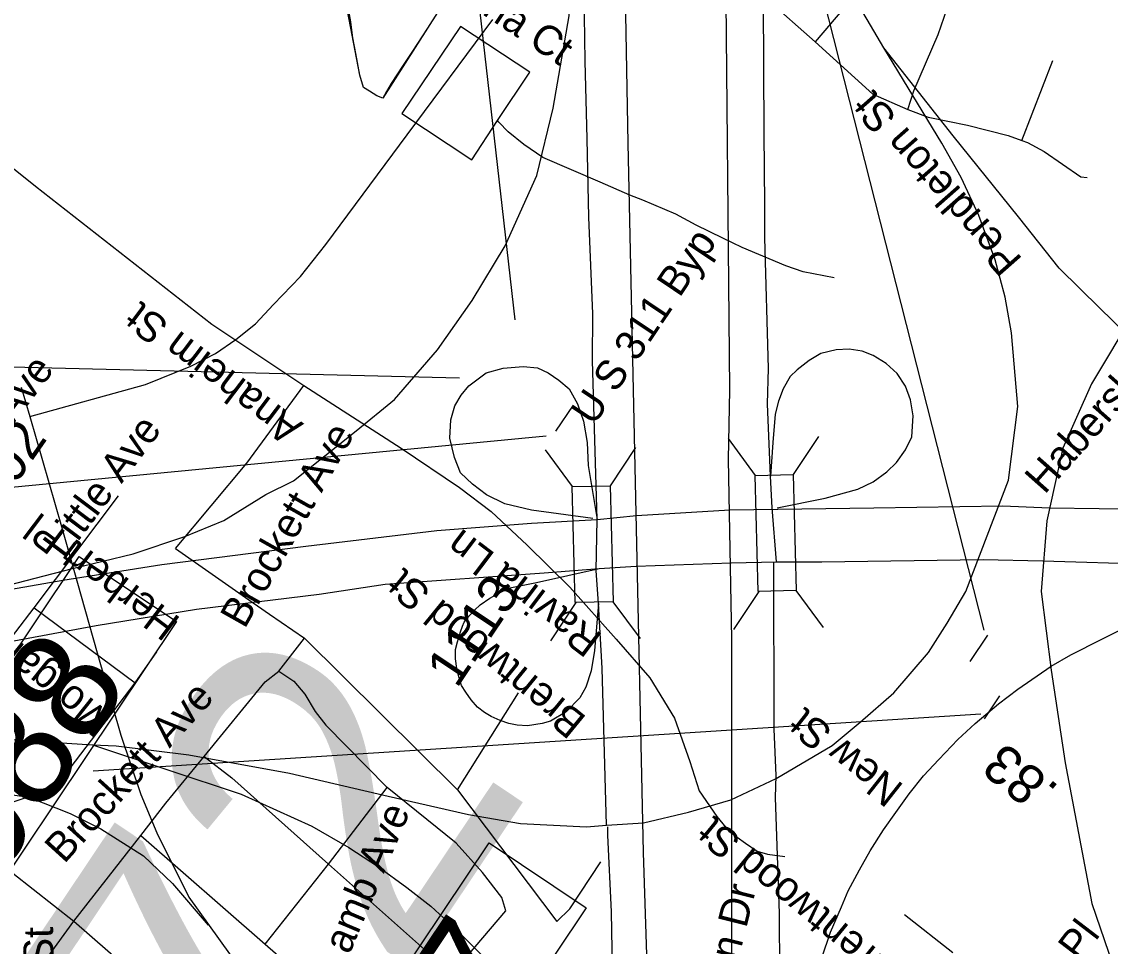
# Model space of a CAD drawing. Extents: x 1716282 to 1717158, y 799307 to 801078.
# Drawn here: x 1716807.8 to 1716858.4, y 800816.9 to 800859.9 of the extents above; entities that cross this region are included whole.
import ezdxf

# ---------------------------------------------------------------- set-up
doc = ezdxf.new("R2010")
doc.units = 0
for name, color, linetype in [('Exist Hydrographic Misc Water Feature', 7, 'Continuous'), ('Exist Road Non-System Structure Non-Sys Other Number Label', 7, 'Continuous'), ('Exist Road Non-System Type 51', 7, 'Continuous'), ('Exist Road Non-System Type 51 Label', 7, 'Continuous'), ('Exist Road Primary Interstate Divided Center Attributed', 7, 'Continuous'), ('Exist Road Primary US Mileage Hundredths English Label', 7, 'Continuous'), ('Exist Road Primary US Structure Ovrhead Sign CELL', 7, 'Continuous'), ('Exist Road Primary US Structure Standard Bridge CELL', 7, 'Continuous'), ('Exist Road Primary US Structure Standard Bridge Number Label', 7, 'Continuous'), ('Exist Road Secondary Mileage Hundredths English Label', 7, 'Continuous'), ('Exist Road Secondary Type 51 Attributed', 7, 'Continuous'), ('Exist Road Secondary Type 51 Label', 7, 'Continuous'), ('Exist Road Secondary Type 51 Number Label', 7, 'Continuous'), ('Prop Road Primary US Projected', 7, 'Continuous'), ('Prop Road Secondary Projected', 7, 'Continuous')]:
    doc.layers.add(name, color=color, linetype=linetype)

msp = doc.modelspace()

# ---------------------------------------------------------------- linework, layer by layer
at = {"layer": 'Exist Hydrographic Misc Water Feature'}
for points in [[(1716823.233, 800862.91), (1716824.255, 800862.247), (1716825.709, 800861.29), (1716826.428, 800860.798), (1716827.147, 800860.308), (1716826.681, 800859.574), (1716824.599, 800856.321), (1716824.327, 800856.437), (1716823.975, 800856.643), (1716823.711, 800856.822), (1716823.54, 800857.395), (1716822.742, 800861.525), (1716822.712, 800861.686), (1716822.675, 800861.888), (1716822.839, 800862.231), (1716823.233, 800862.91)], [(1716827.147, 800860.308), (1716826.681, 800859.574), (1716825.984, 800858.502), (1716825.509, 800857.807), (1716824.994, 800857.001), (1716824.771, 800856.626), (1716824.599, 800856.321), (1716824.327, 800856.437), (1716823.975, 800856.643), (1716823.711, 800856.822), (1716823.54, 800857.395), (1716823.352, 800858.403), (1716823.215, 800859.129), (1716823.118, 800859.861), (1716823.019, 800860.386)], [(1716829.931, 800855.28), (1716831.427, 800857.524), (1716828.208, 800859.652), (1716825.484, 800855.611), (1716828.726, 800853.466), (1716829.931, 800855.28)], [(1716829.931, 800855.28), (1716831.427, 800857.524), (1716828.208, 800859.652), (1716825.484, 800855.611), (1716828.726, 800853.466), (1716829.931, 800855.28)], [(1716845.561, 800847.974), (1716844.107, 800848.264), (1716843.306, 800848.53), (1716841.289, 800849.383), (1716840.391, 800849.818), (1716839.152, 800850.421), (1716838.199, 800850.93), (1716836.679, 800851.583), (1716836.07, 800851.823), (1716834.684, 800852.419), (1716832.027, 800853.568), (1716831.14, 800854.172), (1716830.422, 800854.767), (1716829.984, 800855.207), (1716829.931, 800855.28)]]:
    msp.add_lwpolyline(points, dxfattribs=at)
at = {"layer": 'Exist Road Non-System Type 51'}
for p, q in [((1716854.265, 800854.359), (1716855.704, 800858.076)), ((1716808.41, 800832.66), (1716812.329, 800837.86)), ((1716805.745, 800829.179), (1716808.41, 800832.66)), ((1716808.41, 800832.66), (1716813.104, 800829.18)), ((1716819.776, 800829.711), (1716820.96, 800831.254)), ((1716820.96, 800831.254), (1716828.064, 800824.21)), ((1716813.104, 800829.18), (1716814.114, 800830.611)), ((1716828.064, 800824.21), (1716830.9, 800828.713)), ((1716822.072, 800820.759), (1716824.808, 800824.306)), ((1716828.064, 800824.21), (1716832.672, 800818.094)), ((1716810.25, 800818.107), (1716813.36, 800822.088)), ((1716813.36, 800822.088), (1716819.133, 800817.038)), ((1716819.133, 800817.038), (1716822.072, 800820.759)), ((1716822.072, 800820.759), (1716827.817, 800815.664)), ((1716848.826, 800818.414), (1716851.061, 800816.654)), ((1716802.788, 800807.834), (1716810.25, 800818.107))]:
    msp.add_line(p, q, dxfattribs=at)
for points in [[(1716840.974, 800868.035), (1716840.586, 800867.521), (1716840.278, 800866.959), (1716840.076, 800866.425), (1716839.917, 800865.803), (1716839.861, 800865.241), (1716839.873, 800864.692), (1716839.976, 800864.115), (1716840.168, 800863.552), (1716840.468, 800862.952), (1716840.826, 800862.447), (1716842.433, 800860.936), (1716844.665, 800858.939)], [(1716840.974, 800868.035), (1716845.966, 800863.948), (1716846.281, 800863.367), (1716846.454, 800862.83), (1716846.515, 800862.307), (1716846.49, 800861.77), (1716846.34, 800861.162), (1716846.004, 800860.497), (1716844.665, 800858.939)], [(1716848.968, 800855.797), (1716849.253, 800856.669), (1716850.387, 800859.273), (1716850.933, 800860.903), (1716851.242, 800862.225), (1716851.753, 800863.344), (1716852.404, 800864.507), (1716854.837, 800867.959)], [(1716844.665, 800858.939), (1716847.35, 800856.514), (1716848.968, 800855.797)], [(1716804.298, 800855.582), (1716808.47, 800852.236), (1716816.668, 800845.833), (1716820.932, 800842.974)], [(1716848.968, 800855.797), (1716849.923, 800855.437), (1716851.75, 800855.068), (1716853.627, 800854.59), (1716854.265, 800854.359)], [(1716854.265, 800854.359), (1716854.528, 800854.266), (1716855.303, 800853.843), (1716857.01, 800852.664), (1716857.295, 800852.638)], [(1716814.979, 800835.408), (1716818.285, 800839.376), (1716820.932, 800842.974)], [(1716820.932, 800842.974), (1716825.447, 800840.074), (1716828.156, 800838.249), (1716829.636, 800837.129), (1716831.295, 800835.57), (1716833.276, 800833.613), (1716835.44, 800831.205), (1716836.997, 800829.413), (1716838.142, 800827.539), (1716838.851, 800825.526), (1716839.284, 800824.155), (1716840.112, 800822.97), (1716840.662, 800822.288), (1716841.437, 800821.726), (1716841.972, 800821.363), (1716842.452, 800821.21), (1716843.257, 800821.116)], [(1716814.979, 800835.408), (1716818.225, 800833.135), (1716819.34, 800832.365), (1716820.96, 800831.254)], [(1716816.315, 800825.759), (1716819.145, 800829.226), (1716819.776, 800829.711)], [(1716819.776, 800829.711), (1716820.476, 800829.251), (1716820.976, 800828.651), (1716821.459, 800827.839), (1716821.961, 800827.208), (1716824.808, 800824.306)], [(1716805.53, 800823.194), (1716805.651, 800823.27), (1716806.881, 800823.467), (1716808.088, 800823.868), (1716808.782, 800824.164), (1716809.374, 800824.597), (1716810.094, 800825.215), (1716813.104, 800829.18)], [(1716813.36, 800822.088), (1716814.53, 800823.591), (1716816.315, 800825.759)], [(1716816.315, 800825.759), (1716817.591, 800824.757), (1716822.072, 800820.759)], [(1716827.817, 800815.664), (1716830.319, 800818.587), (1716830.133, 800819.206), (1716829.227, 800820.363), (1716828.002, 800821.728), (1716824.808, 800824.306)], [(1716805.53, 800823.194), (1716805.985, 800822.026), (1716806.553, 800821.114), (1716807.43, 800820.339), (1716810.25, 800818.107)], [(1716832.672, 800818.094), (1716833.275, 800818.674), (1716834.718, 800820.864)], [(1716810.25, 800818.107), (1716815.846, 800813.236), (1716821.85, 800808.173)], [(1716819.133, 800817.038), (1716821.639, 800814.851), (1716824.604, 800812.138), (1716824.843, 800811.954)]]:
    msp.add_lwpolyline(points, dxfattribs=at)
at = {"layer": 'Exist Road Primary Interstate Divided Center Attributed'}
for points in [[(1716835.088, 800891.145), (1716835.541, 800878.131), (1716835.978, 800854.231), (1716836.687, 800821.294), (1716837.624, 800792.348), (1716838.004, 800777.763)], [(1716841.689, 800787.175), (1716841.484, 800799.653), (1716840.807, 800814.818), (1716840.802, 800831.22), (1716840.65, 800839.538), (1716840.717, 800842.78), (1716840.511, 800864.16), (1716840.671, 800880.306), (1716840.628, 800887.437)]]:
    msp.add_lwpolyline(points, dxfattribs=at)
at = {"layer": 'Exist Road Primary US Structure Ovrhead Sign CELL'}
for p, q in [((1716852.51, 800831.62), (1716841.591, 800874.712)), ((1716832.638, 800840.854), (1716833.454, 800842.073)), ((1716832.181, 800840.62), (1716789.715, 800836.557)), ((1716851.867, 800830.16), (1716852.683, 800831.379)), ((1716852.537, 800827.5), (1716853.251, 800828.566)), ((1716852.36, 800827.723), (1716811.161, 800825.07))]:
    msp.add_line(p, q, dxfattribs=at)
for points in [[(1716797.767, 800816.005), (1716810.51, 800835.044), (1716815.018, 800832.027), (1716802.275, 800812.988)], [(1716816.789, 800802.697), (1716829.532, 800821.736), (1716834.041, 800818.718), (1716821.298, 800799.679)]]:
    msp.add_lwpolyline(points, close=True, dxfattribs=at)
at = {"layer": 'Exist Road Primary US Structure Standard Bridge CELL'}
for p, q in [((1716840.635, 800840.516), (1716841.894, 800838.805)), ((1716844.833, 800840.617), (1716843.657, 800838.847)), ((1716832.138, 800839.997), (1716833.398, 800838.286)), ((1716836.337, 800840.097), (1716835.16, 800838.328)), ((1716842.055, 800833.416), (1716840.879, 800831.647)), ((1716843.778, 800833.457), (1716845.038, 800831.746)), ((1716833.559, 800832.897), (1716832.382, 800831.127)), ((1716835.281, 800832.938), (1716836.541, 800831.227))]:
    msp.add_line(p, q, dxfattribs=at)
for points in [[(1716843.657, 800838.847), (1716843.786, 800833.457), (1716842.024, 800833.415), (1716841.894, 800838.805)], [(1716835.16, 800838.328), (1716835.29, 800832.938), (1716833.527, 800832.896), (1716833.398, 800838.286)]]:
    msp.add_lwpolyline(points, close=True, dxfattribs=at)
at = {"layer": 'Exist Road Primary US Structure Standard Bridge Number Label'}
for p, q in [((1716830.747, 800846.028), (1716823.628, 800908.497)), ((1716828.153, 800843.315), (1716779.047, 800844.528))]:
    msp.add_line(p, q, dxfattribs=at)
at = {"layer": 'Exist Road Secondary Type 51 Attributed'}
for points in [[(1716808.212, 800841.546), (1716813.579, 800843.028), (1716815.694, 800843.878), (1716816.837, 800844.472), (1716817.779, 800845.122), (1716818.689, 800845.845), (1716819.532, 800846.746), (1716820.776, 800848.047), (1716821.952, 800849.525), (1716825.733, 800854.617), (1716829.709, 800859.979)], [(1716866.929, 800856.114), (1716859.517, 800846.414), (1716857.495, 800843.059), (1716856.168, 800840.069), (1716855.423, 800836.689), (1716855.159, 800833.411), (1716855.622, 800829.765), (1716856.274, 800825.451), (1716857.521, 800818.927), (1716859.245, 800813.862)], [(1716807.818, 800842.898), (1716808.212, 800841.546)], [(1716808.212, 800841.546), (1716809.683, 800836.43), (1716811.339, 800830.567), (1716812.444, 800826.739), (1716813.373, 800823.985), (1716814.114, 800822.208), (1716815.603, 800819.227), (1716817.482, 800816.585), (1716819.823, 800813.508), (1716821.402, 800811.391), (1716823.302, 800808.909), (1716827.341, 800803.694), (1716829.62, 800800.758), (1716830.806, 800799.28), (1716831.881, 800798.264), (1716833.003, 800797.371)]]:
    msp.add_lwpolyline(points, dxfattribs=at)
at = {"layer": 'Prop Road Primary US Projected'}
for p, q in [((1716842.676, 800837.3), (1716842.604, 800838.776)), ((1716834.544, 800836.759), (1716836.383, 800836.951)), ((1716836.383, 800836.951), (1716840.703, 800837.214)), ((1716842.871, 800834.795), (1716842.676, 800837.3)), ((1716853.388, 800837.387), (1716855.547, 800837.307)), ((1716834.5, 800834.387), (1716834.544, 800836.759)), ((1716852.469, 800834.893), (1716855.245, 800834.841)), ((1716806.138, 800833.439), (1716810.2, 800834.484)), ((1716834.611, 800832.862), (1716834.5, 800834.387)), ((1716834.637, 800834.486), (1716836.36, 800834.587)), ((1716836.36, 800834.587), (1716840.778, 800834.741)), ((1716840.778, 800834.741), (1716842.871, 800834.795)), ((1716840.752, 800823.742), (1716842.861, 800824.726)), ((1716834.98, 800822.561), (1716836.695, 800822.674))]:
    msp.add_line(p, q, dxfattribs=at)
for points in [[(1716842.604, 800838.776), (1716842.457, 800842.135), (1716842.509, 800843.769), (1716842.33, 800849.839), (1716842.329, 800851.392), (1716842.31, 800854.694), (1716842.267, 800860.849), (1716842.2, 800863.488), (1716842.116, 800868.054), (1716842.062, 800872.07), (1716842.093, 800873.711)], [(1716847.862, 800858.655), (1716846.267, 800861.383), (1716845.473, 800862.779), (1716844.924, 800863.943), (1716844.223, 800865.675), (1716843.636, 800867.231), (1716843.232, 800868.564), (1716842.716, 800870.67), (1716842.093, 800873.711)], [(1716810.2, 800834.484), (1716813.012, 800835.161), (1716815.408, 800835.967), (1716817.214, 800836.715), (1716819.171, 800837.915), (1716820.456, 800838.56), (1716823.368, 800840.868), (1716825.149, 800842.337), (1716827.137, 800844.644), (1716828.756, 800846.931), (1716830.273, 800849.463), (1716831.752, 800852.732), (1716832.514, 800855.858), (1716833.258, 800860.15), (1716833.72, 800866.937)], [(1716834.544, 800836.759), (1716834.334, 800844.144), (1716834.353, 800846.313), (1716834.166, 800850.802), (1716834.09, 800854.434), (1716833.999, 800858.044), (1716833.925, 800862.262), (1716833.72, 800866.937)], [(1716842.861, 800824.726), (1716845.466, 800826.262), (1716846.761, 800827.35), (1716848.316, 800828.712), (1716849.93, 800830.58), (1716850.799, 800831.938), (1716851.667, 800833.417), (1716853.646, 800838.577), (1716854.081, 800842.003), (1716853.789, 800845.431), (1716853.491, 800847.09), (1716853.03, 800848.809), (1716852.277, 800850.867), (1716851.445, 800852.633), (1716850.559, 800854.234), (1716847.862, 800858.655)], [(1716859.032, 800845.464), (1716857.901, 800846.554), (1716855.998, 800848.425), (1716854.111, 800850.818), (1716851.078, 800854.575), (1716847.862, 800858.655)], [(1716842.915, 800837.307), (1716845.13, 800837.751), (1716846.66, 800838.169), (1716847.362, 800838.5), (1716847.997, 800838.972), (1716848.449, 800839.407), (1716848.871, 800839.989), (1716849.152, 800840.601), (1716849.228, 800841.576), (1716849.101, 800842.322), (1716848.872, 800842.947), (1716848.484, 800843.541), (1716847.968, 800844.003), (1716847.367, 800844.367), (1716846.856, 800844.571), (1716846.25, 800844.663), (1716845.643, 800844.637), (1716844.937, 800844.462), (1716844.388, 800844.141), (1716843.84, 800843.703), (1716843.513, 800843.391), (1716843.191, 800842.822), (1716842.964, 800842.247), (1716842.822, 800841.655), (1716842.707, 800840.338), (1716842.604, 800838.776)], [(1716834.343, 800836.811), (1716831.499, 800837.184), (1716830.269, 800837.487), (1716829.407, 800837.901), (1716828.762, 800838.398), (1716828.208, 800838.932), (1716827.931, 800839.638), (1716827.715, 800840.531), (1716827.762, 800841.379), (1716827.943, 800842.039), (1716828.237, 800842.527), (1716828.598, 800842.969), (1716829.395, 800843.575), (1716830.191, 800843.791), (1716831.114, 800843.857), (1716831.789, 800843.796), (1716832.284, 800843.562), (1716832.779, 800843.231), (1716833.251, 800842.818), (1716833.64, 800842.134), (1716833.916, 800841.33), (1716834.095, 800840.332), (1716834.13, 800839.266), (1716834.544, 800836.759)], [(1716840.703, 800837.214), (1716847.398, 800837.3), (1716853.388, 800837.387)], [(1716855.547, 800837.307), (1716860.159, 800837.233), (1716865.942, 800836.799), (1716873.016, 800836.329), (1716881.402, 800835.489)], [(1716773.518, 800824.935), (1716780.996, 800827.293), (1716786.539, 800828.95), (1716792.522, 800830.4), (1716796.449, 800831.364), (1716805.234, 800833.158), (1716809.754, 800833.947), (1716814.34, 800834.669), (1716821.027, 800835.516), (1716827.101, 800836.241), (1716831.497, 800836.58), (1716834.544, 800836.759)], [(1716842.871, 800834.795), (1716844.975, 800834.791), (1716852.469, 800834.893)], [(1716811.293, 800831.841), (1716815.957, 800832.589), (1716821.648, 800833.296), (1716824.713, 800833.753), (1716832.092, 800834.283), (1716834.637, 800834.486)], [(1716834.611, 800832.862), (1716834.427, 800830.679), (1716834.27, 800829.731), (1716834.019, 800828.974), (1716833.754, 800828.482), (1716833.12, 800827.821), (1716832.384, 800827.389), (1716831.997, 800827.28), (1716831.312, 800827.17), (1716830.842, 800827.2), (1716830.453, 800827.289), (1716830.05, 800827.42), (1716829.635, 800827.612), (1716829.316, 800827.791), (1716829.003, 800828.044), (1716828.698, 800828.386), (1716828.448, 800828.734), (1716828.26, 800829.057), (1716828.132, 800829.445), (1716828.033, 800829.838), (1716827.981, 800830.287), (1716827.981, 800830.726), (1716828.062, 800831.077), (1716828.201, 800831.543), (1716828.303, 800831.811), (1716828.381, 800831.991), (1716828.514, 800832.178), (1716828.852, 800832.554), (1716829.115, 800832.792), (1716829.574, 800833.105), (1716830.077, 800833.38), (1716830.502, 800833.578), (1716831.732, 800833.827), (1716834.637, 800834.486)], [(1716842.859, 800824.87), (1716842.762, 800827.019), (1716842.751, 800834.792)], [(1716855.245, 800834.841), (1716860.327, 800834.676), (1716864.467, 800834.715), (1716868.213, 800834.315), (1716874.271, 800833.772)], [(1716855.622, 800829.942), (1716856.541, 800830.473), (1716857.975, 800831.203), (1716859.738, 800832.086), (1716861.49, 800832.586), (1716863.083, 800833.01), (1716864.977, 800833.451), (1716866.813, 800833.64), (1716868.397, 800833.779), (1716874.271, 800833.772)], [(1716834.98, 800822.561), (1716834.783, 800829.856), (1716834.611, 800832.862)], [(1716746.206, 800807.301), (1716748.75, 800809.402), (1716750.319, 800810.627), (1716751.951, 800811.796), (1716755.308, 800813.943), (1716758.37, 800815.777), (1716760.379, 800816.993), (1716762.19, 800817.914), (1716765.92, 800819.667), (1716770.8, 800821.603), (1716776.106, 800823.485), (1716783.304, 800825.604), (1716792.794, 800828.038), (1716805.216, 800830.706), (1716811.293, 800831.841)], [(1716843.112, 800804.031), (1716843.563, 800808.479), (1716843.65, 800810.819), (1716843.899, 800812.183), (1716844.432, 800814.275), (1716844.645, 800815.333), (1716844.977, 800816.401), (1716845.382, 800817.602), (1716845.891, 800818.77), (1716846.202, 800819.507), (1716846.736, 800820.495), (1716847.228, 800821.365), (1716847.85, 800822.349), (1716848.421, 800823.148), (1716849.043, 800824.022), (1716849.706, 800824.85), (1716850.415, 800825.612), (1716851.297, 800826.548), (1716852.098, 800827.284), (1716853.181, 800828.196), (1716854.079, 800828.885), (1716855.622, 800829.942)], [(1716771.68, 800821.618), (1716781.819, 800824.307), (1716788.943, 800825.566), (1716793.421, 800826.226), (1716795.819, 800826.513), (1716798.843, 800826.696), (1716806.109, 800826.625), (1716811.123, 800826.296), (1716812.227, 800826.25)], [(1716811.123, 800826.296), (1716818.018, 800823.996), (1716821.298, 800822.513), (1716823.016, 800821.534), (1716824.398, 800820.632), (1716825.713, 800819.662), (1716826.833, 800818.801), (1716828.03, 800817.688), (1716829.098, 800816.616), (1716830.012, 800815.647), (1716830.71, 800814.822), (1716831.957, 800813.184), (1716832.506, 800812.437), (1716833.198, 800811.237), (1716833.854, 800809.95), (1716834.29, 800808.833), (1716834.709, 800807.592), (1716835.159, 800805.863), (1716835.465, 800804.586)], [(1716812.227, 800826.25), (1716815.598, 800825.822), (1716820.262, 800824.971), (1716824.853, 800823.916), (1716828.572, 800823.066), (1716830.998, 800822.64), (1716834.05, 800822.49), (1716834.98, 800822.561)], [(1716843.107, 800808.53), (1716843.052, 800812.953), (1716843.012, 800818.463), (1716842.832, 800823.847), (1716842.859, 800824.87)], [(1716836.695, 800822.674), (1716838.789, 800823.164), (1716840.752, 800823.742)], [(1716835.465, 800804.586), (1716835.224, 800818.534), (1716835.05, 800822.097), (1716835.051, 800822.482)]]:
    msp.add_lwpolyline(points, dxfattribs=at)
at = {"layer": 'Prop Road Secondary Projected'}
msp.add_lwpolyline([(1716773.852, 800811.968), (1716774.744, 800814.697), (1716775.939, 800816.71), (1716777.73, 800818.931), (1716779.729, 800820.556), (1716782.079, 800822.023), (1716784.2, 800822.58), (1716785.794, 800822.805), (1716791.173, 800823.688), (1716797.06, 800824.08), (1716800.265, 800824.215), (1716802.928, 800824.332), (1716804.942, 800824.276), (1716806.431, 800824.116), (1716808.165, 800823.867), (1716810.09, 800823.111), (1716811.507, 800822.39), (1716813.485, 800821.143), (1716814.831, 800819.862), (1716816.491, 800817.914)], dxfattribs=at)

# ---------------------------------------------------------------- texts
at = {"layer": 'Exist Road Non-System Structure Non-Sys Other Number Label'}
msp.add_text('J572', height=15.223, rotation=56.2051, dxfattribs=at).set_placement((1716807.118, 800787.797))
at = {"layer": 'Exist Road Non-System Type 51 Label'}
for s, rotation, p in [('Sapona Ct', 326.3007, (1716825.592, 800862.633)), ('Pendleton St', 131.3961, (1716854.336, 800848.845)), ('U S 311 Byp', 56.2051, (1716834.39, 800841.065)), ('Habersham Rd', 48.4355, (1716855.319, 800837.885)), ('Anaheim St', 143.0271, (1716820.956, 800841.2)), ('Willard Ave', 52.7017, (1716803.746, 800836.309)), ('Little Ave', 53.0635, (1716809.823, 800834.878)), ('Brockett Ave', 60.5842, (1716818.186, 800831.639)), ('Herbert Pl', 142.9868, (1716815.272, 800832.143)), ('Ravina Ln', 142.9253, (1716834.858, 800831.379)), ('Brentwood St', 140.7308, (1716834.113, 800827.553)), ('Morgan Pl', 141.5656, (1716812.128, 800827.639)), ('Brockett Ave', 47.7257, (1716809.807, 800820.735)), ('New St', 141.7034, (1716848.84, 800824.398)), ('Lamb Ave', 66.9807, (1716822.644, 800815.58)), ('Brentwood St', 140.7308, (1716848.519, 800816.035)), ('Wade Pl', 52.5599, (1716853.708, 800811.953)), ('Gordon St', 90.6546, (1716809.386, 800809.449))]:
    msp.add_text(s, height=1.3775, rotation=rotation, dxfattribs=at).set_placement(p)
at = {"layer": 'Exist Road Primary US Mileage Hundredths English Label'}
msp.add_text('.83', height=1.8125, rotation=140.6418, dxfattribs=at).set_placement((1716856.058, 800824.328))
at = {"layer": 'Exist Road Primary US Structure Ovrhead Sign CELL'}
for s, p in [('S1088', (1716802.006, 800812.888)), ('S1077', (1716821.028, 800799.579))]:
    msp.add_text(s, height=5.075, rotation=56.2051, dxfattribs=at).set_placement(p)
at = {"layer": 'Exist Road Secondary Mileage Hundredths English Label'}
msp.add_text('.02', height=1.8125, rotation=55.3005, dxfattribs=at).set_placement((1716807.142, 800837.755))
at = {"layer": 'Exist Road Secondary Type 51 Label'}
msp.add_text('E Green Dr', height=1.3775, rotation=75.8693, dxfattribs=at).set_placement((1716839.669, 800810.596))
at = {"layer": 'Exist Road Secondary Type 51 Number Label'}
msp.add_text('1113', height=1.8125, rotation=56.2051, dxfattribs=at).set_placement((1716828.033, 800828.878))

doc.saveas('drawing.dxf')
